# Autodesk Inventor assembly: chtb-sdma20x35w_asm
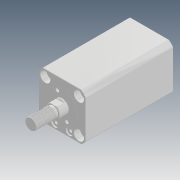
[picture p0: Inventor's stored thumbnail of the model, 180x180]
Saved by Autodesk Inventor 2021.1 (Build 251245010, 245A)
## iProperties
Company: Microsoft
Created: 2018-05
Part Number: chtb-sdma20x35w_asm
Description: STEP AP214
Document SubType Name: Assembly
Designer: user
Title: chtb-sdma20x35w_asm.STEP
Author: Windows
Revision Number: ÈÎºÎ
Sending System: SolidWorks 2015
Preprocessor: SwSTEP 2.0
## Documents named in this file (4)
- D:\Vault_2016\Projekty\Clamptek\Hydraulic\CHTB\CHTB-20\Inventor\CHTB-SDMA20x35W\chtb-sdma20x35w_asm.iam
- D:\Vault_2016\Projekty\Clamptek\Hydraulic\CHTB\CHTB-20\Inventor\CHTB-SDMA20x35W\CHTB-SDMA20X35NBT.ipt
- D:\Vault_2016\Projekty\Clamptek\Hydraulic\CHTB\CHTB-20\Inventor\CHTB-SDMA20x35W\CHTB-SDMA20X35WHSG.ipt
- D:\Vault_2016\Projekty\Clamptek\Hydraulic\CHTB\CHTB-20\Inventor\CHTB-SDMA20x35W\QG_3.ipt
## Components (3 placed, 3 different names)
1. CHTB-SDMA20X35NBT_1
2. CHTB-SDMA20X35WHSG_2
3. QG_3_3
